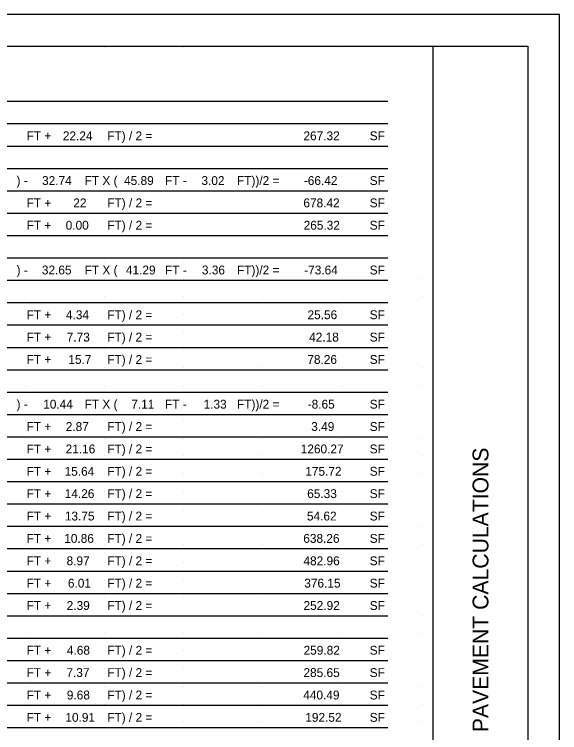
# Model space of a CAD drawing. Extents: x 2073163.5 to 2073197.5, y 634076.4 to 634098.4.
# Drawn here: x 2073188.9 to 2073197.51, y 634087.09 to 634098.43 of the extents above; entities that cross this region are included whole.
import ezdxf

# ---------------------------------------------------------------- set-up
doc = ezdxf.new("R2010")
doc.units = 0
for name, color, linetype in [('SC_Scratch1', 7, 'Continuous'), ('SH_Border', 7, 'Continuous'), ('SH_Cut_Line', 7, 'Continuous'), ('SH_Data', 7, 'Continuous'), ('SH_Text', 7, 'Continuous')]:
    doc.layers.add(name, color=color, linetype=linetype)

msp = doc.modelspace()

# ---------------------------------------------------------------- linework, layer by layer
at = {"layer": 'SC_Scratch1'}
for p, q in [((2073180.369, 634097.061), (2073194.796, 634097.061)), ((2073180.369, 634096.708), (2073194.796, 634096.708)), ((2073180.369, 634096.354), (2073194.796, 634096.354)), ((2073180.369, 634096.001), (2073194.796, 634096.001)), ((2073180.369, 634095.648), (2073194.796, 634095.648)), ((2073180.369, 634095.294), (2073194.796, 634095.294)), ((2073180.369, 634094.941), (2073194.796, 634094.941)), ((2073180.369, 634094.588), (2073194.796, 634094.588)), ((2073180.369, 634094.234), (2073194.796, 634094.234)), ((2073180.369, 634093.881), (2073194.796, 634093.881)), ((2073180.369, 634093.528), (2073194.796, 634093.528)), ((2073180.369, 634093.174), (2073194.796, 634093.174)), ((2073180.369, 634092.821), (2073194.796, 634092.821)), ((2073180.369, 634092.468), (2073194.796, 634092.468)), ((2073180.369, 634092.114), (2073194.796, 634092.114)), ((2073180.369, 634091.761), (2073194.796, 634091.761)), ((2073180.369, 634091.407), (2073194.796, 634091.407)), ((2073180.369, 634091.054), (2073194.796, 634091.054)), ((2073180.369, 634090.701), (2073194.796, 634090.701)), ((2073180.369, 634090.347), (2073194.796, 634090.347)), ((2073180.369, 634089.994), (2073194.796, 634089.994)), ((2073180.369, 634089.641), (2073194.796, 634089.641)), ((2073180.369, 634089.287), (2073194.796, 634089.287)), ((2073180.369, 634088.934), (2073194.796, 634088.934)), ((2073180.369, 634088.581), (2073194.796, 634088.581)), ((2073180.369, 634088.227), (2073194.796, 634088.227)), ((2073180.369, 634087.874), (2073194.796, 634087.874)), ((2073180.369, 634087.521), (2073194.796, 634087.521)), ((2073180.369, 634087.167), (2073194.796, 634087.167))]:
    msp.add_line(p, q, dxfattribs=at)
at = {"layer": 'SH_Border'}
msp.add_line((2073195.507, 634076.934), (2073195.507, 634097.934), dxfattribs=at)
msp.add_lwpolyline([(2073165.007, 634097.934), (2073197.007, 634097.934), (2073197.007, 634076.934), (2073165.007, 634076.934)], close=True, dxfattribs=at)
at = {"layer": 'SH_Cut_Line'}
msp.add_lwpolyline([(2073163.507, 634076.434), (2073197.507, 634076.434), (2073197.507, 634098.434), (2073163.507, 634098.434)], close=True, dxfattribs=at)
at = {"layer": 'SH_Data'}
for p, q in [((2073189.071, 634097.91), (2073189.071, 634097.91)), ((2073190.321, 634097.91), (2073190.321, 634097.91)), ((2073191.571, 634097.91), (2073191.571, 634097.91)), ((2073192.821, 634097.91), (2073192.821, 634097.91)), ((2073194.071, 634097.91), (2073194.071, 634097.91)), ((2073195.321, 634097.91), (2073195.321, 634097.91)), ((2073189.071, 634094.538), (2073189.071, 634094.538)), ((2073190.321, 634094.538), (2073190.321, 634094.538)), ((2073191.571, 634094.538), (2073191.571, 634094.538)), ((2073192.821, 634094.538), (2073192.821, 634094.538)), ((2073194.071, 634094.538), (2073194.071, 634094.538)), ((2073195.321, 634094.538), (2073195.321, 634094.538)), ((2073189.071, 634094.258), (2073189.071, 634094.258)), ((2073190.321, 634094.258), (2073190.321, 634094.258)), ((2073191.571, 634094.258), (2073191.571, 634094.258)), ((2073192.821, 634094.258), (2073192.821, 634094.258)), ((2073194.071, 634094.258), (2073194.071, 634094.258)), ((2073195.321, 634094.258), (2073195.321, 634094.258)), ((2073189.071, 634093.978), (2073189.071, 634093.978)), ((2073190.321, 634093.978), (2073190.321, 634093.978)), ((2073191.571, 634093.978), (2073191.571, 634093.978)), ((2073192.821, 634093.978), (2073192.821, 634093.978)), ((2073194.071, 634093.978), (2073194.071, 634093.978)), ((2073195.321, 634093.978), (2073195.321, 634093.978)), ((2073189.071, 634093.698), (2073189.071, 634093.698)), ((2073190.321, 634093.698), (2073190.321, 634093.698)), ((2073191.571, 634093.698), (2073191.571, 634093.698)), ((2073192.821, 634093.698), (2073192.821, 634093.698)), ((2073194.071, 634093.698), (2073194.071, 634093.698)), ((2073195.321, 634093.698), (2073195.321, 634093.698)), ((2073189.071, 634093.418), (2073189.071, 634093.418)), ((2073190.321, 634093.418), (2073190.321, 634093.418)), ((2073191.571, 634093.418), (2073191.571, 634093.418)), ((2073192.821, 634093.418), (2073192.821, 634093.418)), ((2073194.071, 634093.418), (2073194.071, 634093.418)), ((2073195.321, 634093.418), (2073195.321, 634093.418)), ((2073189.071, 634093.138), (2073189.071, 634093.138)), ((2073190.321, 634093.138), (2073190.321, 634093.138)), ((2073191.571, 634093.138), (2073191.571, 634093.138)), ((2073192.821, 634093.138), (2073192.821, 634093.138)), ((2073194.071, 634093.138), (2073194.071, 634093.138)), ((2073195.321, 634093.138), (2073195.321, 634093.138)), ((2073189.071, 634092.858), (2073189.071, 634092.858)), ((2073190.321, 634092.858), (2073190.321, 634092.858)), ((2073191.571, 634092.858), (2073191.571, 634092.858)), ((2073192.821, 634092.858), (2073192.821, 634092.858)), ((2073194.071, 634092.858), (2073194.071, 634092.858)), ((2073195.321, 634092.858), (2073195.321, 634092.858)), ((2073189.071, 634092.578), (2073189.071, 634092.578)), ((2073190.321, 634092.578), (2073190.321, 634092.578)), ((2073191.571, 634092.578), (2073191.571, 634092.578)), ((2073192.821, 634092.578), (2073192.821, 634092.578)), ((2073194.071, 634092.578), (2073194.071, 634092.578)), ((2073195.321, 634092.578), (2073195.321, 634092.578)), ((2073189.071, 634092.298), (2073189.071, 634092.298)), ((2073190.321, 634092.298), (2073190.321, 634092.298)), ((2073191.571, 634092.298), (2073191.571, 634092.298)), ((2073192.821, 634092.298), (2073192.821, 634092.298)), ((2073194.071, 634092.298), (2073194.071, 634092.298)), ((2073195.321, 634092.298), (2073195.321, 634092.298)), ((2073189.071, 634092.018), (2073189.071, 634092.018)), ((2073190.321, 634092.018), (2073190.321, 634092.018)), ((2073191.571, 634092.018), (2073191.571, 634092.018)), ((2073192.821, 634092.018), (2073192.821, 634092.018)), ((2073194.071, 634092.018), (2073194.071, 634092.018)), ((2073195.321, 634092.018), (2073195.321, 634092.018)), ((2073189.071, 634091.738), (2073189.071, 634091.738)), ((2073190.321, 634091.738), (2073190.321, 634091.738)), ((2073191.571, 634091.738), (2073191.571, 634091.738)), ((2073192.821, 634091.738), (2073192.821, 634091.738)), ((2073194.071, 634091.738), (2073194.071, 634091.738)), ((2073195.321, 634091.738), (2073195.321, 634091.738)), ((2073189.071, 634091.458), (2073189.071, 634091.458)), ((2073190.321, 634091.458), (2073190.321, 634091.458)), ((2073191.571, 634091.458), (2073191.571, 634091.458)), ((2073192.821, 634091.458), (2073192.821, 634091.458)), ((2073194.071, 634091.458), (2073194.071, 634091.458)), ((2073195.321, 634091.458), (2073195.321, 634091.458)), ((2073189.071, 634091.178), (2073189.071, 634091.178)), ((2073190.321, 634091.178), (2073190.321, 634091.178)), ((2073191.571, 634091.178), (2073191.571, 634091.178)), ((2073192.821, 634091.178), (2073192.821, 634091.178)), ((2073194.071, 634091.178), (2073194.071, 634091.178)), ((2073195.321, 634091.178), (2073195.321, 634091.178)), ((2073189.071, 634090.898), (2073189.071, 634090.898)), ((2073190.321, 634090.898), (2073190.321, 634090.898)), ((2073191.571, 634090.898), (2073191.571, 634090.898)), ((2073192.821, 634090.898), (2073192.821, 634090.898)), ((2073194.071, 634090.898), (2073194.071, 634090.898)), ((2073195.321, 634090.898), (2073195.321, 634090.898)), ((2073189.071, 634090.618), (2073189.071, 634090.618)), ((2073190.321, 634090.618), (2073190.321, 634090.618)), ((2073191.571, 634090.618), (2073191.571, 634090.618)), ((2073192.821, 634090.618), (2073192.821, 634090.618)), ((2073194.071, 634090.618), (2073194.071, 634090.618)), ((2073195.321, 634090.618), (2073195.321, 634090.618)), ((2073189.071, 634090.338), (2073189.071, 634090.338)), ((2073190.321, 634090.338), (2073190.321, 634090.338)), ((2073191.571, 634090.338), (2073191.571, 634090.338)), ((2073192.821, 634090.338), (2073192.821, 634090.338)), ((2073194.071, 634090.338), (2073194.071, 634090.338)), ((2073195.321, 634090.338), (2073195.321, 634090.338)), ((2073189.071, 634090.058), (2073189.071, 634090.058)), ((2073190.321, 634090.058), (2073190.321, 634090.058)), ((2073191.571, 634090.058), (2073191.571, 634090.058)), ((2073192.821, 634090.058), (2073192.821, 634090.058)), ((2073194.071, 634090.058), (2073194.071, 634090.058)), ((2073195.321, 634090.058), (2073195.321, 634090.058)), ((2073189.071, 634089.778), (2073189.071, 634089.778)), ((2073190.321, 634089.778), (2073190.321, 634089.778)), ((2073191.571, 634089.778), (2073191.571, 634089.778)), ((2073192.821, 634089.778), (2073192.821, 634089.778)), ((2073194.071, 634089.778), (2073194.071, 634089.778)), ((2073195.321, 634089.778), (2073195.321, 634089.778)), ((2073189.071, 634089.498), (2073189.071, 634089.498)), ((2073190.321, 634089.498), (2073190.321, 634089.498)), ((2073191.571, 634089.498), (2073191.571, 634089.498)), ((2073192.821, 634089.498), (2073192.821, 634089.498)), ((2073194.071, 634089.498), (2073194.071, 634089.498)), ((2073195.321, 634089.498), (2073195.321, 634089.498)), ((2073189.071, 634089.218), (2073189.071, 634089.218)), ((2073190.321, 634089.218), (2073190.321, 634089.218)), ((2073191.571, 634089.218), (2073191.571, 634089.218)), ((2073192.821, 634089.218), (2073192.821, 634089.218)), ((2073194.071, 634089.218), (2073194.071, 634089.218)), ((2073195.321, 634089.218), (2073195.321, 634089.218)), ((2073189.071, 634088.938), (2073189.071, 634088.938)), ((2073190.321, 634088.938), (2073190.321, 634088.938)), ((2073191.571, 634088.938), (2073191.571, 634088.938)), ((2073192.821, 634088.938), (2073192.821, 634088.938)), ((2073194.071, 634088.938), (2073194.071, 634088.938)), ((2073195.321, 634088.938), (2073195.321, 634088.938)), ((2073189.071, 634088.658), (2073189.071, 634088.658)), ((2073190.321, 634088.658), (2073190.321, 634088.658)), ((2073191.571, 634088.658), (2073191.571, 634088.658)), ((2073192.821, 634088.658), (2073192.821, 634088.658)), ((2073194.071, 634088.658), (2073194.071, 634088.658)), ((2073195.321, 634088.658), (2073195.321, 634088.658)), ((2073189.071, 634088.378), (2073189.071, 634088.378)), ((2073190.321, 634088.378), (2073190.321, 634088.378)), ((2073191.571, 634088.378), (2073191.571, 634088.378)), ((2073192.821, 634088.378), (2073192.821, 634088.378)), ((2073194.071, 634088.378), (2073194.071, 634088.378)), ((2073195.321, 634088.378), (2073195.321, 634088.378)), ((2073189.071, 634088.098), (2073189.071, 634088.098)), ((2073190.321, 634088.098), (2073190.321, 634088.098)), ((2073191.571, 634088.098), (2073191.571, 634088.098)), ((2073192.821, 634088.098), (2073192.821, 634088.098)), ((2073194.071, 634088.098), (2073194.071, 634088.098)), ((2073195.321, 634088.098), (2073195.321, 634088.098)), ((2073189.071, 634087.818), (2073189.071, 634087.818)), ((2073190.321, 634087.818), (2073190.321, 634087.818)), ((2073191.571, 634087.818), (2073191.571, 634087.818)), ((2073192.821, 634087.818), (2073192.821, 634087.818)), ((2073194.071, 634087.818), (2073194.071, 634087.818)), ((2073195.321, 634087.818), (2073195.321, 634087.818)), ((2073189.071, 634087.538), (2073189.071, 634087.538)), ((2073190.321, 634087.538), (2073190.321, 634087.538)), ((2073191.571, 634087.538), (2073191.571, 634087.538)), ((2073192.821, 634087.538), (2073192.821, 634087.538)), ((2073194.071, 634087.538), (2073194.071, 634087.538)), ((2073195.321, 634087.538), (2073195.321, 634087.538)), ((2073189.071, 634087.258), (2073189.071, 634087.258)), ((2073190.321, 634087.258), (2073190.321, 634087.258)), ((2073191.571, 634087.258), (2073191.571, 634087.258)), ((2073192.821, 634087.258), (2073192.821, 634087.258)), ((2073194.071, 634087.258), (2073194.071, 634087.258)), ((2073195.321, 634087.258), (2073195.321, 634087.258))]:
    msp.add_line(p, q, dxfattribs=at)

# ---------------------------------------------------------------- texts
msp.add_text('PAVEMENT CALCULATIONS', height=0.25, rotation=90, dxfattribs=at).set_placement((2073196.382, 634087.095))
at = {"layer": 'SH_Text'}
for s, p in [('FT +', (2073189.089, 634096.446)), ('22.24', (2073189.662, 634096.446)), ('FT) / 2 =', (2073190.362, 634096.446)), ('267.32', (2073193.461, 634096.446)), ('SF ', (2073194.507, 634096.446)), (') - ', (2073188.93, 634095.739)), ('32.74', (2073189.333, 634095.739)), ('FT X (', (2073190.005, 634095.739)), ('45.89', (2073190.628, 634095.739)), ('FT -', (2073191.275, 634095.739)), ('3.02', (2073191.85, 634095.739)), ('FT))/2 =', (2073192.411, 634095.739)), ('-66.42', (2073193.467, 634095.739)), ('SF ', (2073194.507, 634095.739)), ('FT +', (2073189.089, 634095.386)), ('22', (2073189.826, 634095.386)), ('FT) / 2 =', (2073190.362, 634095.386)), ('678.42', (2073193.46, 634095.386)), ('SF ', (2073194.507, 634095.386)), ('FT +', (2073189.089, 634095.033)), ('0.00', (2073189.706, 634095.033)), ('FT) / 2 =', (2073190.362, 634095.033)), ('265.32', (2073193.464, 634095.033)), ('SF ', (2073194.507, 634095.033)), (') - ', (2073188.93, 634094.326)), ('32.65', (2073189.33, 634094.326)), ('FT X (', (2073190.005, 634094.326)), ('41.29', (2073190.657, 634094.326)), ('FT -', (2073191.275, 634094.326)), ('3.36', (2073191.857, 634094.326)), ('FT))/2 =', (2073192.411, 634094.326)), ('-73.64', (2073193.473, 634094.326)), ('SF ', (2073194.507, 634094.326)), ('FT +', (2073189.089, 634093.619)), ('4.34', (2073189.71, 634093.619)), ('FT) / 2 =', (2073190.362, 634093.619)), ('25.56', (2073193.525, 634093.619)), ('SF ', (2073194.507, 634093.619)), ('FT +', (2073189.089, 634093.266)), ('7.73', (2073189.723, 634093.266)), ('FT) / 2 =', (2073190.362, 634093.266)), ('42.18', (2073193.551, 634093.266)), ('SF ', (2073194.507, 634093.266)), ('FT +', (2073189.089, 634092.913)), ('15.7', (2073189.748, 634092.913)), ('FT) / 2 =', (2073190.362, 634092.913)), ('78.26', (2073193.522, 634092.913)), ('SF ', (2073194.507, 634092.913)), (') - ', (2073188.93, 634092.206)), ('10.44', (2073189.351, 634092.206)), ('FT X (', (2073190.005, 634092.206)), ('7.11', (2073190.742, 634092.206)), ('FT -', (2073191.275, 634092.206)), ('1.33', (2073191.884, 634092.206)), ('FT))/2 =', (2073192.411, 634092.206)), ('-8.65', (2073193.528, 634092.206)), ('SF ', (2073194.507, 634092.206)), ('FT +', (2073189.089, 634091.853)), ('2.87', (2073189.707, 634091.853)), ('FT) / 2 =', (2073190.362, 634091.853)), ('3.49', (2073193.584, 634091.853)), ('SF ', (2073194.507, 634091.853)), ('FT +', (2073189.089, 634091.499)), ('21.16', (2073189.705, 634091.499)), ('FT) / 2 =', (2073190.362, 634091.499)), ('1260.27', (2073193.418, 634091.499)), ('SF ', (2073194.507, 634091.499)), ('FT +', (2073189.089, 634091.146)), ('15.64', (2073189.689, 634091.146)), ('FT) / 2 =', (2073190.362, 634091.146)), ('175.72', (2073193.49, 634091.146)), ('SF ', (2073194.507, 634091.146)), ('FT +', (2073189.089, 634090.793)), ('14.26', (2073189.691, 634090.793)), ('FT) / 2 =', (2073190.362, 634090.793)), ('65.33', (2073193.52, 634090.793)), ('SF ', (2073194.507, 634090.793)), ('FT +', (2073189.089, 634090.439)), ('13.75', (2073189.693, 634090.439)), ('FT) / 2 =', (2073190.362, 634090.439)), ('54.62', (2073193.516, 634090.439)), ('SF ', (2073194.507, 634090.439)), ('FT +', (2073189.089, 634090.086)), ('10.86', (2073189.683, 634090.086)), ('FT) / 2 =', (2073190.362, 634090.086)), ('638.26', (2073193.458, 634090.086)), ('SF ', (2073194.507, 634090.086)), ('FT +', (2073189.089, 634089.732)), ('8.97', (2073189.72, 634089.732)), ('FT) / 2 =', (2073190.362, 634089.732)), ('482.96', (2073193.461, 634089.732)), ('SF ', (2073194.507, 634089.732)), ('FT +', (2073189.089, 634089.379)), ('6.01', (2073189.741, 634089.379)), ('FT) / 2 =', (2073190.362, 634089.379)), ('376.15', (2073193.474, 634089.379)), ('SF ', (2073194.507, 634089.379)), ('FT +', (2073189.089, 634089.026)), ('2.39', (2073189.722, 634089.026)), ('FT) / 2 =', (2073190.362, 634089.026)), ('252.92', (2073193.462, 634089.026)), ('SF ', (2073194.507, 634089.026)), ('FT +', (2073189.089, 634088.319)), ('4.68', (2073189.725, 634088.319)), ('FT) / 2 =', (2073190.362, 634088.319)), ('259.82', (2073193.463, 634088.319)), ('SF ', (2073194.507, 634088.319)), ('FT) / 2 =', (2073190.362, 634087.966)), ('FT +', (2073189.089, 634087.966)), ('7.37', (2073189.718, 634087.966)), ('285.65', (2073193.461, 634087.966)), ('SF ', (2073194.507, 634087.966)), ('FT +', (2073189.089, 634087.612)), ('9.68', (2073189.724, 634087.612)), ('FT) / 2 =', (2073190.362, 634087.612)), ('440.49', (2073193.458, 634087.612)), ('SF ', (2073194.507, 634087.612)), ('FT +', (2073189.089, 634087.259)), ('10.91', (2073189.701, 634087.259)), ('FT) / 2 =', (2073190.362, 634087.259)), ('192.52', (2073193.49, 634087.259)), ('SF ', (2073194.507, 634087.259))]:
    msp.add_text(s, height=0.14, rotation=0.0001, dxfattribs=at).set_placement(p)

doc.saveas('drawing.dxf')
